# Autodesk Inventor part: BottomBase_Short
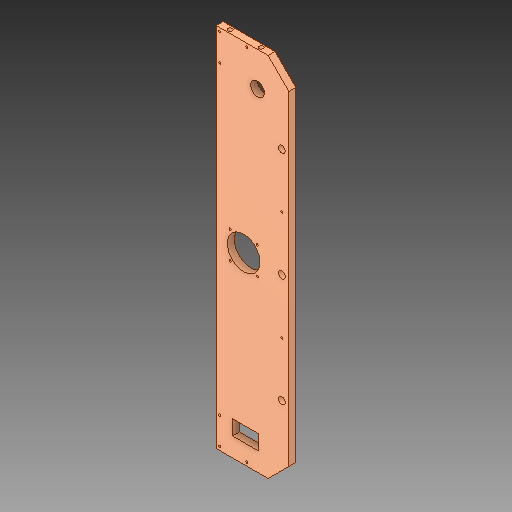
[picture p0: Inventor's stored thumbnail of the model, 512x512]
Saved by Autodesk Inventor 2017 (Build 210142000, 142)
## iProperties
Created: 2017-04
Part Number: BottomBase_Short
Material: Generic
Document SubType Name: Modeling
Designer: John
Density: 1 g/cm^3
Appearance: Default
Mass: 1053.8 g
Surface Area: 1959.41 cm^2
Volume: 1053.8 cm^3
Sending System: NX 10.0.2.6
NX_MaterialMissingAssignments: TRUE
NX_MaterialMultipleAssigned: FALSE
Author: jledden
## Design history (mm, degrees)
feature "SOLID1"
body "Solid1"
